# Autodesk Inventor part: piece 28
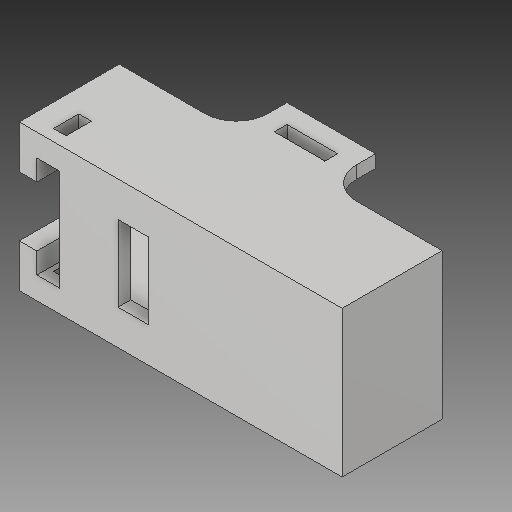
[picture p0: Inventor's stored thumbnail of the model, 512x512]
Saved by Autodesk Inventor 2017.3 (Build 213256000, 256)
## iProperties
Created: 2002-06
Part Number: piece 28
Material: Générique
Document SubType Name: Modeling
Designer: ficho
Density: 1 g/cm^3
Appearance: Par défaut
Author: ficho
Sending System: SolidWorks 2009
Last Author: christophe
Last Saved: 2011-02-10
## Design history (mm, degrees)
feature "Enlèv. mat.-Extru.4"
node "Solide1"
